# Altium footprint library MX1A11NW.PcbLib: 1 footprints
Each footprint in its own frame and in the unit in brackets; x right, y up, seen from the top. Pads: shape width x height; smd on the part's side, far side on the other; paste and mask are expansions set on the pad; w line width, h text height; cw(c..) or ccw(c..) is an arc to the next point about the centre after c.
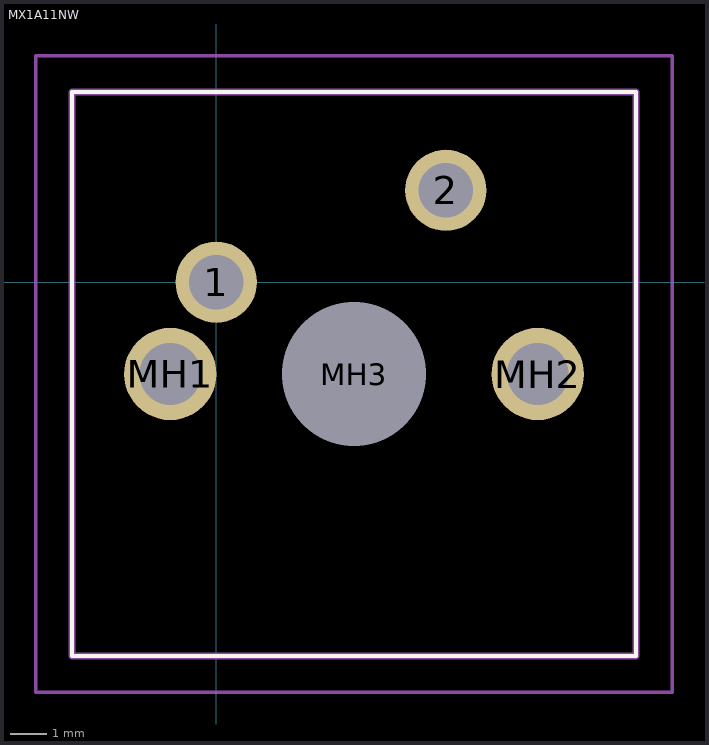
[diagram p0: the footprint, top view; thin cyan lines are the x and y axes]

## MX1A11NW [mil]
pads (5):
  round 88.5 hole 59: 1(0,0) 2(250,100)
  round 100.51 hole 67: MH1(-50,-100) MH2(350,-100)
  round 78.5 hole 157 unplated: MH3(150,-100)
Top Overlay:
  lines w3.94: -157.09,-407.09 457.09,-407.09 457.09,207.09 -157.09,207.09 -157.09,-407.09
Mechanical 15:
  lines w7.87: -157.09,-407.09 457.09,-407.09 457.09,207.09 -157.09,207.09 -157.09,-407.09
Mechanical 20:
  lines w3.94: -196.46,-446.46 496.46,-446.46 496.46,246.46 -196.46,246.46 -196.46,-446.46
